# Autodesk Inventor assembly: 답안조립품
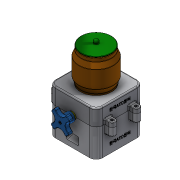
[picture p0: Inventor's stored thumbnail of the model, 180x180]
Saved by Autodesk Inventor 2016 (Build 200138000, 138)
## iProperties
Created: 2018-01
Part Number: 답안조립품
Material: 일반
Document SubType Name: Assembly
Designer: Administrator
Author: Administrator
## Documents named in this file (9)
- C:\Users\Administrator\Desktop\480107V1035\답안조립품.iam
- C:\Users\Administrator\Desktop\480107V1035\본체.ipt
- C:\Users\Administrator\Desktop\480107V1035\핸들축.ipt
- C:\Users\Administrator\Desktop\480107V1035\핸들.ipt
- C:\Users\Administrator\Desktop\480107V1035\볼트 M3x12.ipt
- C:\Users\Administrator\Desktop\480107V1035\본체커버.ipt
- C:\Users\Administrator\Desktop\480107V1035\용기.ipt
- C:\Users\Administrator\Desktop\480107V1035\용기캡.ipt
- C:\Users\Administrator\Desktop\480107V1035\볼트 M4x12.ipt
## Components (2 placed, 2 different names)
1. 핸들축:1
2. 핸들:1
